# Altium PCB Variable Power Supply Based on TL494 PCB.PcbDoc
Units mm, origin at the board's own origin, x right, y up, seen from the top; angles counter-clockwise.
Board outline 100 x 100 mm, 2 copper layers (Top Layer, Bottom Layer); 50 components, 0 nets, 131 pads, 0 vias.
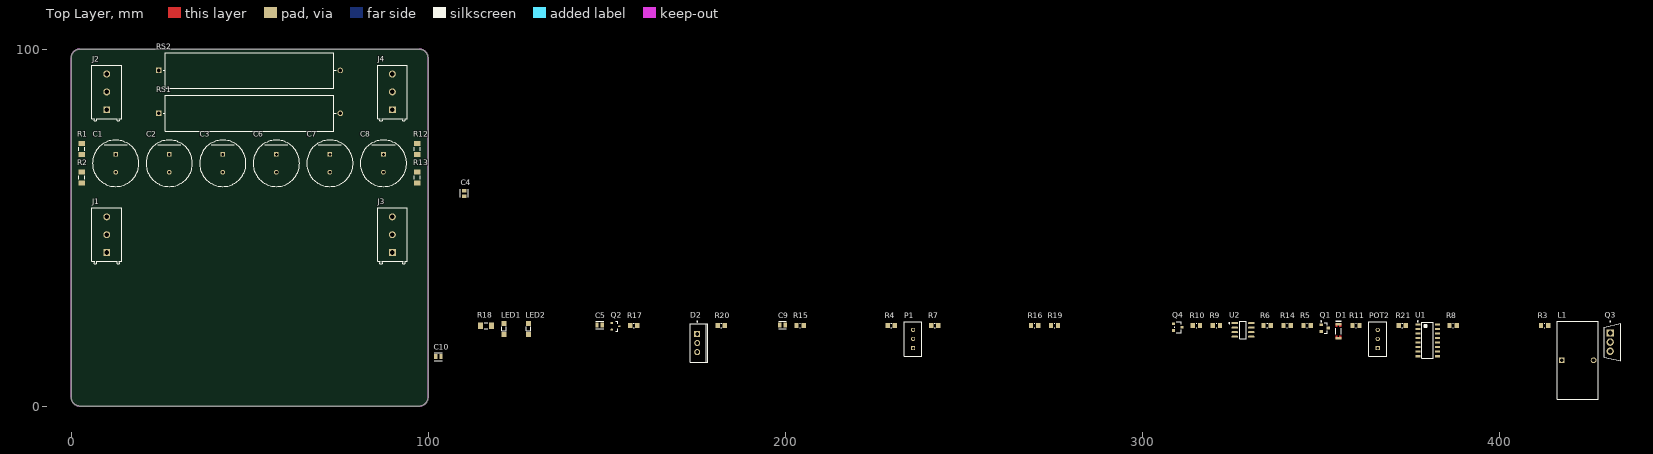
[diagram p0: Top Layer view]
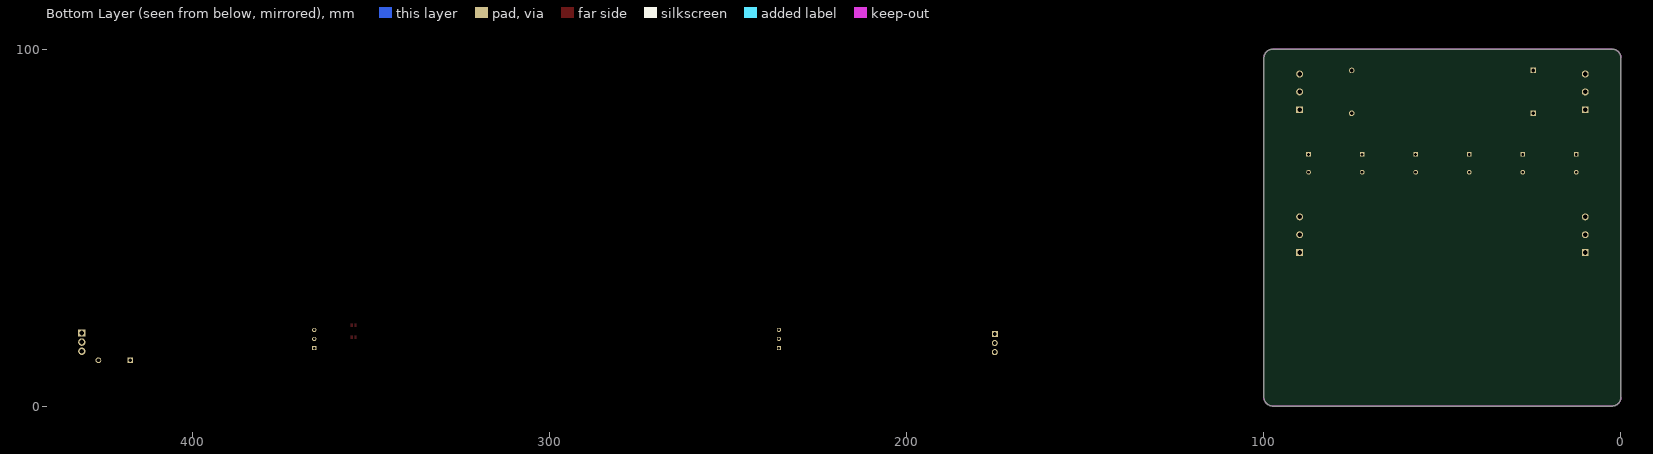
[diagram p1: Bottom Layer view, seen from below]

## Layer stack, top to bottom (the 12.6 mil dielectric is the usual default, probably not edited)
Top Solder: solder mask 0.0102, Solder Resist, Dk 3.5
Top Layer: signal copper 0.0356
Dielectric 1: dielectric 0.32, FR-4, Dk 4.8
Bottom Layer: signal copper 0.0356
Bottom Solder: solder mask 0.0102, Solder Resist, Dk 3.5

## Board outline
0,2.5 0,97.5 cw(c2.5,97.5) 2.5,100 97.5,100 cw(c97.5,97.5) 100,97.5 100,2.5 cw(c97.5,2.5) 97.5,0 2.5,0 cw(c2.5,2.5)

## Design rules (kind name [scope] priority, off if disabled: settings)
Clearance [All] p1: gap=0.254 ignorepadtopadclearanceinfootprint=FALSE except(0: Arc-Hole Track-Hole SMDPad-Hole THPad-Hole Via-Hole Fill-Hole Poly-Hole Region-Hole Text-Hole)
PolygonConnect [All] p1: connectstyle=Relief reliefconductorwidth=0.254 reliefentries=4 polygonreliefangle="90 Angle" airgapwidth=0.254
RoutingVias [All] p1: holewidth=0.711 width=1.27 viastyle="Through Hole" minholewidth=0.711 minwidth=1.27 maxholewidth=0.711 maxwidth=1.27
SolderMaskExpansion [All] p1: expansion=0.102 istentingtop=FALSE
Width [All] p1: maxlimit=0.254 minlimit=0.254 preferedwidth=0.254
30 further rules are at their usual default settings.

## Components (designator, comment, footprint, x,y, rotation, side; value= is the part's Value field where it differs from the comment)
C1 "680uF 35V" FP-EEU-FM1V681B-MFG 12.5,68 r270 top
C2 "680uF 35V" FP-EEU-FM1V681B-MFG 27.5,68 r270 top
C3 "680uF 35V" FP-EEU-FM1V681B-MFG 42.5,68 r270 top
C4 "100nf" FP-C0805C-DG-MFG 110.109,59.575 r90 top value=10uF
C5 "10nf" FP-C0805C-DG-MFG 148.082,22.733 r0 top value=10uF
C6 "680uF 35V" FP-EEU-FM1V681B-MFG 57.5,68 r270 top
C7 "680uF 35V" FP-EEU-FM1V681B-MFG 72.5,68 r270 top
C8 "680uF 35V" FP-EEU-FM1V681B-MFG 87.5,68 r270 top
C9 "10nf" FP-C0805C-DG-MFG 199.263,22.733 r0 top value=10uF
C10 "100nf" FP-C0805C-DG-MFG 102.87,13.843 r0 top value=10uF
D1 "18V" FAIR-LL-34_V 354.965,20.955 r90 top
D2 "MBRF20100" ONSC-TO-220FP-3-221D-03 175.387,17.653 r0 top
J1 "691213710003" 691213710003 10,48 r90 top
J2 "691213710003" 691213710003 10,88 r90 top
J3 "691213710003" 691213710003 90,48 r90 top
J4 "691213710003" 691213710003 90,88 r90 top
L1 "2114-V-RC" FP-2114-V-RC-MFG 422.021,12.827 r90 top value=150uH
LED1 "CV" 1206_A 121.285,21.59 r90 top
LED2 "CC" 1206_A 128.143,21.59 r90 top
P1 "100K" FP-3296W-MFG 235.839,18.796 r0 top
POT2 "100K" FP-3296W-MFG 366.014,18.796 r0 top
Q1 "3904 NPN" ONSC-SOT-23-3-318-08_V 351.155,21.844 r0 top
Q2 "3906 PNP" FP-PG-SOT23-3-IPC_C 152.527,22.352 r0 top
Q3 "IRF4905PBF" FP-T14-0413-MFG 431.8,17.907 r0 top
Q4 "AO3400A" FP-SOT23-MFG 310.007,22.098 r0 top
R1 "1.5KΩ" RESC3216X60X45ML15T20 3,72 r90 top
R2 "1.5KΩ" RESC3216X60X45ML15T20 3,64 r90 top
R3 "150KΩ" RESC2013X60X35ML10T20 412.75,22.606 r0 top
R4 "39KΩ" RESC2013X60X35ML10T20 229.743,22.606 r0 top
R5 "510Ω" RESC2013X60X35ML10T20 346.202,22.606 r0 top
R6 "51KΩ" RESC2013X60X35ML10T20 335.026,22.606 r0 top
R7 "10KΩ" RESC2013X60X35ML10T20 241.935,22.606 r0 top
R8 "10KΩ" RESC2013X60X35ML10T20 387.096,22.606 r0 top
R9 "100Ω" RESC2013X60X35ML10T20 320.802,22.606 r0 top
R10 "100Ω" RESC2013X60X35ML10T20 315.214,22.606 r0 top
R11 "10KΩ" RESC2013X60X35ML10T20 359.918,22.606 r0 top
R12 "1.5KΩ" RESC3216X60X45ML15T20 97,72 r90 top
R13 "1.5KΩ" RESC3216X60X45ML15T20 97,64 r90 top
R14 "150KΩ" RESC2013X60X35ML10T20 340.614,22.606 r0 top
R15 "39KΩ" RESC2013X60X35ML10T20 204.216,22.606 r0 top
R16 "100Ω" RESC2013X60X35ML10T20 269.875,22.606 r0 top
R17 "1KΩ" RESC2013X60X35ML10T20 157.607,22.606 r0 top
R18 "18Ω" RESC3216X60X45ML15T20 116.205,22.479 r0 top
R19 "3.9KΩ" RESC2013X60X35ML10T20 275.463,22.606 r0 top
R20 "3.9KΩ" RESC2013X60X35ML10T20 182.118,22.606 r0 top
R21 "NC" RESC2013X60X35ML10T20 372.872,22.606 r0 top
RS1 "0.1Ω" FP-20-MFG 50,82 r0 top value=20000Ω
RS2 "0.1Ω" FP-20-MFG 50,94 r0 top value=20000Ω
U1 "TL494CDR" D0016A_N 379.984,18.415 r0 top
U2 "LM358DR2G" FP-751-07-IPC_C 328.295,21.336 r0 top

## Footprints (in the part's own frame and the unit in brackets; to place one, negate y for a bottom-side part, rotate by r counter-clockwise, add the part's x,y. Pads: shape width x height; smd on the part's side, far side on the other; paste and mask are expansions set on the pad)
1206_A [mm] "Chip LED, 2-Leads, Body 3.2x1.6mm, IPC Medium Density"
  rect 1.4x1.5 smd: 1(-1.5,0) 2(1.5,0)
  silkscreen extent -0.5,-0.67 0.6,0.65, body extent -1.6,-0.8 1.6,0.8, height 0.68
691213710003 [mm] "5,00mm - modular - green - Horizontal entry with rising cage clamp -  10,0mm height - 03p"
  rect 1.95x1.95 hole 1.3: 1(-5,0)
  round 1.95 hole 1.3: 2(0,0) 3(5,0)
  silkscreen extent -8.1,-4.15 7.5,4.15, body extent -8.1,-4.15 7.5,4.15, height 10.05
D0016A_N [mm] "SOIC, 16-Leads, Body 10x4mm, Pitch 1.27mm, IPC Medium Density"
  rrect17% 1.45x0.6 smd: 1(-2.725,4.445) 2(-2.725,3.175) 3(-2.725,1.905) 4(-2.725,0.635) 5(-2.725,-0.635) 6(-2.725,-1.905) 7(-2.725,-3.175) 8(-2.725,-4.445) 9(2.725,-4.445) 10(2.725,-3.175) 11(2.725,-1.905) 12(2.725,-0.635) 13(2.725,0.635) 14(2.725,1.905) 15(2.725,3.175) 16(2.725,4.445)
  silkscreen extent -2.85,-5 1.6,5.42, body extent -3,-4.95 3,4.95, height 1.59
FAIR-LL-34_V [mm] "SOD, Body 3.6x1.5 mm"
  rect 0.6x1.65 smd: 1(-1.95,0) 2(1.95,0)
  Top Layer region: 1.125,0.25 2.225,0.25 2.225,0.825 1.125,0.825
  Top Layer region: -2.225,-0.825 -1.125,-0.825 -1.125,-0.25 -2.225,-0.25
  Top Layer region: -2.225,0.25 -1.125,0.25 -1.125,0.825 -2.225,0.825
  Top Layer region: 1.125,-0.825 2.225,-0.825 2.225,-0.25 1.125,-0.25
  silkscreen extent -0.8,-0.75 2.75,0.75, body extent -1.8,-0.75 1.8,0.75, height 1.5
FP-20-MFG [mm]
  rect 1.55x1.55 hole 1 paste-1000 mask+0: 1(-25.412,0)
  round 1.55 hole 1 paste-1000 mask+0: 2(25.412,0)
  silkscreen extent -24.24,-5 24.24,5, body extent -26.29,-5.1 26.29,5.1, height 0.25
FP-751-07-IPC_C [mm]
  rect 1.874x0.543 smd paste+0 mask+0: 1(-2.316,1.905)
  rrect100% 1.874x0.543 smd paste+0 mask+0: 2(-2.316,0.635) 3(-2.316,-0.635) 4(-2.316,-1.905) 5(2.316,-1.905) 6(2.316,-0.635) 7(2.316,0.635) 8(2.316,1.905)
  silkscreen extent -3.98,-2.45 0.88,2.45, body extent -3.35,-2.55 3.35,2.55, height 0.25
FP-2114-V-RC-MFG [mm]
  rect 1.6x1.6 hole 1.05 paste-1000 mask+0: 1(0,4.445)
  round 1.6 hole 1.05 paste-1000 mask+0: 2(0,-4.445)
  silkscreen extent -10.92,-5.72 10.92,5.72, body extent -11.02,-5.81 11.02,5.81, height 0.25
FP-3296W-MFG [mm]
  rect 1.2x1.2 hole 0.7 paste-1000 mask+0: 1(0.005,-2.54)
  round 1.2 hole 0.7 paste-1000 mask+0: 2(0.005,0) 3(0.005,2.54)
  silkscreen extent -2.48,-4.89 2.48,4.89, body extent -2.58,-4.99 2.58,4.99, height 0.25
FP-C0805C-DG-MFG [mm]
  rect 0.95x1.35 smd paste+0 mask+0: 1(-0.75,0) 2(0.75,0)
  silkscreen extent -1.11,-1.08 1.1,1.07, body extent -1.4,-0.85 1.4,0.85, height 0.25
FP-EEU-FM1V681B-MFG [mm]
  rect 1.3x1.3 hole 0.8 paste-1000 mask+0: 1(-2.5,0)
  round 1.3 hole 0.8 paste-1000 mask+0: 2(2.5,0)
  silkscreen extent -6.5,-6.5 6.5,6.5, body extent -6.6,-6.6 6.6,6.6, height 0.25
FP-PG-SOT23-3-IPC_C [mm]
  rect 0.708x0.536 smd paste+0 mask+0: 1(-1.075,0.95)
  rrect100% 0.708x0.536 smd paste+0 mask+0: 2(-1.075,-0.95) 3(1.075,0)
  silkscreen extent 0,-1.45 0.65,1.45, body extent -1.53,-1.55 1.53,1.55, height 0.25
FP-SOT23-MFG [mm]
  rect 0.8x0.8 smd paste+0 mask+0: 1(-1.2,0.95) 2(-1.2,-0.95) 3(1.2,0)
  silkscreen extent -0.9,-1.55 0.9,1.55, body extent -1.7,-1.78 1.7,1.78, height 0.25
FP-T14-0413-MFG [mm]
  rect 2.05x2.05 hole 1.35 paste-1000 mask+0: 1(-0.683,2.54)
  round 2.05 hole 1.35 paste-1000 mask+0: 2(-0.683,0) 3(-0.683,-2.54)
  silkscreen extent -2.32,-5.26 2.32,5.88, body extent -2.42,-5.36 2.42,5.36, height 0.25
ONSC-SOT-23-3-318-08_V [mm] "SOT23, 3-Leads, Body 2.92x1.3mm, Pitch 0.95mm"
  rect 0.9x0.8 smd: 1(-1,0.95) 2(-1,-0.95) 3(1,0)
  silkscreen extent -1.12,-1.46 0.65,2.02, body extent -0.65,-1.46 0.65,1.46, height 1.11
ONSC-TO-220FP-3-221D-03 [mm] "FM, 3-Leads, Body 10.63x4.9mm, Pitch 2.54mm"
  rect 1.7x1.7 hole 1.1: 1(0,2.54)
  round 1.7 hole 1.1: 2(0,0) 3(0,-2.54)
  silkscreen extent -1.89,-5.35 3.01,6.12, body extent -1.89,-5.33 3.01,5.33, height 19.55
RESC2013X60X35ML10T20 [mm] "Chip Resistor, 2-Leads, Body 2.1x1.35mm, IPC Low Density"
  rect 1.2x1.45 smd: 1(-1,0) 2(1,0)
  silkscreen extent -0.1,-0.63 0.1,0.63, body extent -1.05,-0.68 1.05,0.67, height 0.6
RESC3216X60X45ML15T20 [mm] "Chip Resistor, 2-Leads, Body 3.3x1.75mm, IPC Low Density"
  rect 1.35x1.85 smd: 1(-1.525,0) 2(1.525,0)
  silkscreen extent -0.45,-0.82 0.45,0.82, body extent -1.65,-0.87 1.65,0.87, height 0.6

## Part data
C1 C2 C3 C6 C7 C8: library part CMP-05427-000051-1, "CAP ALUM 680UF 20% 35V RADIAL", Capacitance=680uF, Case/Package=Radial, ESR (Equivalent Series Resistance)=18mR, Max Operating Temperature=105°C, Min Operating Temperature=-40°C, Package Quantity=500, Ripple Current=2.6A, Tolerance=20%, Voltage Rating=35V
C4 C5 C9 C10: library part CMP-2007-03243-2, "General Purpose Ceramic Capacitor, 0805, 10nF, 50V", 3DS Part Number=220-00001, Capacitance=10uF, Manufacturer=Kemet, Manufacturer Part Number=C0805C106K8PACTU, Package=C0805C-DG, Temperature="-55°C to +85°C", Temperature Characteristic=X5R, Temperature Coefficient=15%, Temperature Range High=+85°C, Temperature Range Low=-55°C, Tolerance=10%, Voltage=10V
D1: library part CMP-2000-05112-2, "Zener Diode, 500 mW, 18 V, -65 to 175 degC, 2-Pin SMD, RoHS, Tape and Reel", Manufacturer=FairchildSemiconductor, Operating Temperature=-65to175degC, Package=2LL-34, Package Description="2-Leads SOD, Body 3.6x1.5mm", Peak Average Forward Current=0.3A, Peak Forward Voltage=1@0.01AV, Peak Non-Repetitive Surge Current=4A, Peak Reverse Current=5@75VuA, Peak Reverse Repetitive Voltage=100V
D2: library part CMP-1055-00696-1, "SWITCHMODE(TM) Schottky Power Rectifier, 3-Pin TO-220FP, Pb-Free, Tube", Manufacturer="On Semiconductor", PartNumber=MBRF20100CTG
J1 J2 J3 J4: library part CMP-1502-02527-1, "Serie 213 - 5.00 mm Horizontal Entry Modular with RisingCage Clamp WR-TBL, 3 pin", Manufacturer="Wurth Elektronik", Operating Temperature=-40to105degC
L1: library part CMP-07248-000012-1, "FIXED IND 150UH 3.4A 62 MOHM TH", Inductance=150uH, Manufacturer=Bourns, Rms Current=3.4A, Series Resistance=0.062Ω, Temperature="-55°C to +105°C", Temperature Range High=+105°C, Temperature Range Low=-55°C, Test Frequency=1kHz, Tolerance=15%
LED1 LED2: library part CMP-1426-00015-1, "SMD mono-color Chip LED, WL-SMCW, Blue", Color=Blue, Manufacturer="Wuerth Elektronik", PartNumber=150120BS75000
P1: library part CMP-07234-000024-1, "TRIMMER 10K OHM 0.5W PC PIN TOP", Max Operating Temperature=125°C, Max Power Dissipation=500mW, Min Operating Temperature=-55°C, Package Quantity=1, Resistance=10kR, Temperature Coefficient=100ppm/°C, Tolerance=10%
POT2: library part CMP-07234-000024-1, "TRIMMER 100K OHM 0.5W PC PIN TOP", Max Operating Temperature=125°C, Max Power Dissipation=500mW, Min Operating Temperature=-55°C, Package Quantity=1, Resistance=10kR, Temperature Coefficient=100ppm/°C, Tolerance=10%
Q1: library part CMP-1048-00630-1, "General Purpose Transistor, NPN Silicon, 3-Pin SOT-23, Pb-Free, Tape and Reel", Manufacturer="On Semiconductor", PartNumber=MMBT3904LT3G
Q2: library part CMP-32898-000014-1, "TRANS PNP 40V 0.2A SOT23", Case/Package=TO-236-3, Collector Base Voltage (VCBO)=40V, Collector-emitter Voltage-Max=400mV, Current Rating=-200mA, Emitter Base Voltage (VEBO)=6V, Frequency=250MHz, Max Collector Current=200mA, Max Operating Temperature=150°C, Max Power Dissipation=330mW, Min Operating Temperature=-65°C, Voltage Rating (DC)=-40V
Q3: library part CMP-02550-000110-1, "MOSFET P-CH 55V 74A TO-220AB", Continuous Drain Current=-90A, Drain To Source Breakdown Voltage=-60V, Drain To Source Resistance=0.0074Ω, Gate To Source Voltage=20V, Input Capacitace At Vds="9200pF @ -25V", Manufacturer=Vishay, Manufacturer Part Number=SUP90P06-09L-E3, Max Forward Diode Voltage=-1.5V, Max Junction Temp=+175°C, Package=T14-0413, Power Dissipation=2.4W, Pulse Drain Current=-200A, Temperature="-55°C to +175°C", Temperature Range Low=-55°C, Typ Forward Diode Voltage=-1V
Q4: library part CMP-83955-000006-1, "MOSFET N-CH 30V 5.7A SOT23", Case/Package=SOT-23, Continuous Drain Current (ID)=5.7A, Drain to Source Voltage (Vdss)=30V, Gate to Source Voltage (Vgs)=12V, Input Capacitance=630pF, Max Operating Temperature=150°C, Max Power Dissipation=1.4W, Min Operating Temperature=-55°C
R1 R2 R12 R13: library part CMP-2100-03616-1, "Thick Film Resistors, 1206, 1.5KΩ, 1%, 0.125W", Case Code (Imperial)=1206, Case Code (Metric)=3216, Manufacturer="Vishay Semiconductor", Max Operating Temperature=155degC, Max Power Dissipation=250mW, Min Operating Temperature=-55degC, Package Description="2-Pin Surface Mount Device, Body 3.15 x 1.6 mm", Package Quantity=10, Package Reference=1206.0, Resistance=1KOhm, Temperature Coefficient=100ppm/degreesC, Tolerance=1%, Voltage Rating=200V
R3 R14: library part CMP-2100-03673-1, "Thick Film Resistors, 0805, 150KΩ, 5%, 0.125W", Case Code (Imperial)=0805, Case Code (Metric)=2012, Manufacturer=Yageo, Max Operating Temperature=155degC, Min Operating Temperature=-55degC, Package Description="2-Pin Surface Mounted Device, Body 2 x 1.25 mm", Power Rating=125mW, Resistance=0mOhm, Temperature Coefficient=200ppm/degreesC, Tolerance=5%, Voltage Rating=150V
R4 R15: library part CMP-2100-03673-1, "Thick Film Resistors, 0805, 39KΩ, 5%, 0.125W", Case Code (Imperial)=0805, Case Code (Metric)=2012, Manufacturer=Yageo, Max Operating Temperature=155degC, Min Operating Temperature=-55degC, Package Description="2-Pin Surface Mounted Device, Body 2 x 1.25 mm", Power Rating=125mW, Resistance=0mOhm, Temperature Coefficient=200ppm/degreesC, Tolerance=5%, Voltage Rating=150V
R5: library part CMP-2100-03673-1, "Thick Film Resistors, 0805, 510Ω, 5%, 0.125W", Case Code (Imperial)=0805, Case Code (Metric)=2012, Manufacturer=Yageo, Max Operating Temperature=155degC, Min Operating Temperature=-55degC, Package Description="2-Pin Surface Mounted Device, Body 2 x 1.25 mm", Power Rating=125mW, Resistance=0mOhm, Temperature Coefficient=200ppm/degreesC, Tolerance=5%, Voltage Rating=150V
R6: library part CMP-2100-03673-1, "Thick Film Resistors, 0805, 51kΩ, 5%, 0.125W", Case Code (Imperial)=0805, Case Code (Metric)=2012, Manufacturer=Yageo, Max Operating Temperature=155degC, Min Operating Temperature=-55degC, Package Description="2-Pin Surface Mounted Device, Body 2 x 1.25 mm", Power Rating=125mW, Resistance=0mOhm, Temperature Coefficient=200ppm/degreesC, Tolerance=5%, Voltage Rating=150V
R7 R8: library part CMP-2100-03673-1, "Thick Film Resistors, 0805, 10kΩ, 5%, 0.125W", Case Code (Imperial)=0805, Case Code (Metric)=2012, Manufacturer=Yageo, Max Operating Temperature=155degC, Min Operating Temperature=-55degC, Package Description="2-Pin Surface Mounted Device, Body 2 x 1.25 mm", Power Rating=125mW, Resistance=0mOhm, Temperature Coefficient=200ppm/degreesC, Tolerance=5%, Voltage Rating=150V
R9 R10 R16: library part CMP-2100-03673-1, "Thick Film Resistors, 0805, 100Ω, 5%, 0.125W", Case Code (Imperial)=0805, Case Code (Metric)=2012, Manufacturer=Yageo, Max Operating Temperature=155degC, Min Operating Temperature=-55degC, Package Description="2-Pin Surface Mounted Device, Body 2 x 1.25 mm", Power Rating=125mW, Resistance=0mOhm, Temperature Coefficient=200ppm/degreesC, Tolerance=5%, Voltage Rating=150V
R11: library part CMP-2100-03673-1, "Thick Film Resistors, 0805, 10KΩ, 5%, 0.125W", Case Code (Imperial)=0805, Case Code (Metric)=2012, Manufacturer=Yageo, Max Operating Temperature=155degC, Min Operating Temperature=-55degC, Package Description="2-Pin Surface Mounted Device, Body 2 x 1.25 mm", Power Rating=125mW, Resistance=0mOhm, Temperature Coefficient=200ppm/degreesC, Tolerance=5%, Voltage Rating=150V
R17: library part CMP-2100-03673-1, "Thick Film Resistors, 0805, 1KΩ, 5%, 0.125W", Case Code (Imperial)=0805, Case Code (Metric)=2012, Manufacturer=Yageo, Max Operating Temperature=155degC, Min Operating Temperature=-55degC, Package Description="2-Pin Surface Mounted Device, Body 2 x 1.25 mm", Power Rating=125mW, Resistance=0mOhm, Temperature Coefficient=200ppm/degreesC, Tolerance=5%, Voltage Rating=150V
R18: library part CMP-2100-03616-1, "Thick Film Resistors, 1206, 18Ω, 1%, 0.125W", Case Code (Imperial)=1206, Case Code (Metric)=3216, Manufacturer="Vishay Semiconductor", Max Operating Temperature=155degC, Max Power Dissipation=250mW, Min Operating Temperature=-55degC, Package Description="2-Pin Surface Mount Device, Body 3.15 x 1.6 mm", Package Quantity=10, Package Reference=1206.0, Resistance=1KOhm, Temperature Coefficient=100ppm/degreesC, Tolerance=1%, Voltage Rating=200V
R19 R20: library part CMP-2100-03673-1, "Thick Film Resistors, 0805, 3.9KΩ, 5%, 0.125W", Case Code (Imperial)=0805, Case Code (Metric)=2012, Manufacturer=Yageo, Max Operating Temperature=155degC, Min Operating Temperature=-55degC, Package Description="2-Pin Surface Mounted Device, Body 2 x 1.25 mm", Power Rating=125mW, Resistance=0mOhm, Temperature Coefficient=200ppm/degreesC, Tolerance=5%, Voltage Rating=150V
R21: library part CMP-2100-03673-1, "Thick Film Resistors, 0805, NC, 5%, 0.125W", Case Code (Imperial)=0805, Case Code (Metric)=2012, Manufacturer=Yageo, Max Operating Temperature=155degC, Min Operating Temperature=-55degC, Package Description="2-Pin Surface Mounted Device, Body 2 x 1.25 mm", Power Rating=125mW, Resistance=0mOhm, Temperature Coefficient=200ppm/degreesC, Tolerance=5%, Voltage Rating=150V
RS1 RS2: library part CMP-33362-000002-1, "RES 20K OHM 10W 5% AXIAL", Manufacturer=Ohmite, Manufacturer Part Number=20J20K, Package=20, Power Rating=10W, Resistance=20000Ω, Temperature Coefficient=30ppm/°C, Tolerance=5%, Voltage Rating=720V
U1: library part CMP-0319-00950-2, "Pulse-Width-Modulation Control Circuit with Voltage Control, 45 % Duty Cycle, 0 to +70 degC, 16-pin SOIC (D), Green (RoHS & no Sb/Br)", Frequency(Max)(kHz)=300, Manufacturer="Texas Instruments", Rating=Military
U2: library part CMP-1310-00291-2, "IC OPAMP GP 2 CIRCUIT 8SOIC", Case/Package=SOIC, Dual Supply Voltage=9V, Input Bias Current=250nA, Input Offset Voltage (Vos)=7mV, Max Dual Supply Voltage=16V, Max Operating Temperature=70°C, Max Supply Voltage=32V, Min Dual Supply Voltage=1.5V, Min Operating Temperature=0°C, Min Supply Voltage=3V, Nominal Supply Current=1.2mA, Operating Supply Current=1.5mA, Output Current=40mA, Package Quantity=2500, Power Supply Rejection Ratio (PSRR)=65dB, Voltage Gain=100dB

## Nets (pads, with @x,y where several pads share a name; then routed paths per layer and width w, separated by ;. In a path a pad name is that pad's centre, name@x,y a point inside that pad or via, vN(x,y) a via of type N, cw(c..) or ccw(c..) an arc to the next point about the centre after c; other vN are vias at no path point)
pads on no net: C1.1 C1.2 C2.1 C2.2 C3.1 C3.2 C4.1 C4.2 C5.1 C5.2 C6.1 C6.2 C7.1 C7.2 C8.1 C8.2 C9.1 C9.2 C10.1 C10.2 D1.1 D1.2 D2.1 D2.2 D2.3 J1.1 J1.2 J1.3 J2.1 J2.2 J2.3 J3.1 J3.2 J3.3 J4.1 J4.2 J4.3 L1.1 L1.2 LED1.1 LED1.2 LED2.1 LED2.2 P1.1 P1.2 P1.3 POT2.1 POT2.2 POT2.3 Q1.1 Q1.2 Q1.3 Q2.1 Q2.2 Q2.3 Q3.1 Q3.2 Q3.3 Q4.1 Q4.2 Q4.3 R1.1 R1.2 R2.1 R2.2 R3.1 R3.2 R4.1 R4.2 R5.1 R5.2 R6.1 R6.2 R7.1 R7.2 R8.1 R8.2 R9.1 R9.2 R10.1 R10.2 R11.1 R11.2 R12.1 R12.2 R13.1 R13.2 R14.1 R14.2 R15.1 R15.2 R16.1 R16.2 R17.1 R17.2 R18.1 R18.2 R19.1 R19.2 R20.1 R20.2 R21.1 R21.2 RS1.1 RS1.2 RS2.1 RS2.2 U1.1 U1.2 U1.3 U1.4 U1.5 U1.6 U1.7 U1.8 U1.9 U1.10 U1.11 U1.12 U1.13 U1.14 U1.15 U1.16 U2.1 U2.2 U2.3 U2.4 U2.5 U2.6 U2.7 U2.8

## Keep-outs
Keep-Out Layer:
  the board outline again, w0.254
